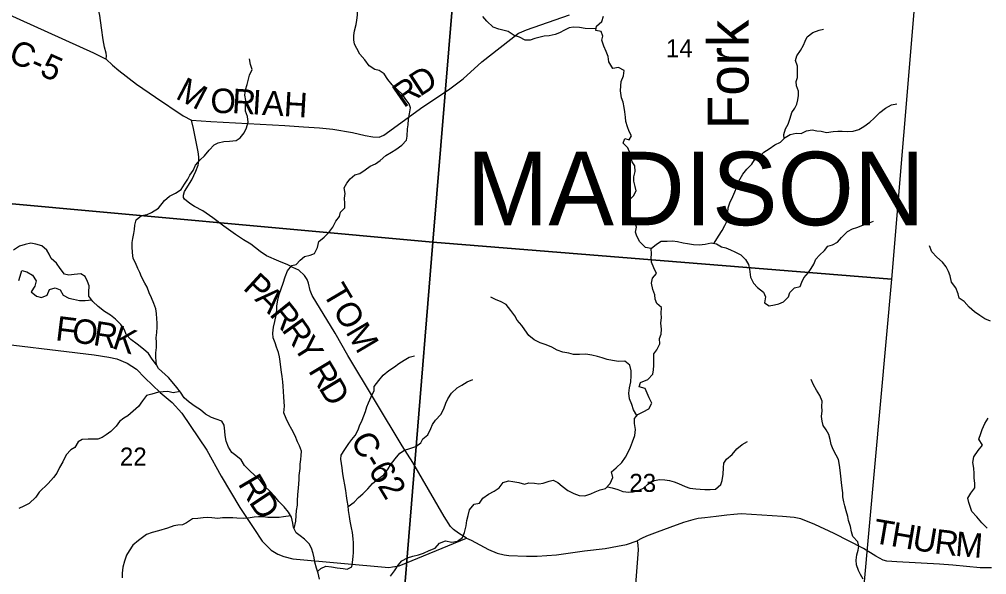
# Model space of a CAD drawing. Extents: x 1715311 to 2083412, y 146837 to 553079.
# Drawn here: x 1966796 to 1978656, y 325907 to 332710 of the extents above; entities that cross this region are included whole.
import ezdxf

# ---------------------------------------------------------------- set-up
doc = ezdxf.new("R2010")
doc.units = 0
for name, color, linetype in [('GM_X_County_Road', 7, 'Continuous'), ('GM_X_County_Road_Text', 7, 'Continuous'), ('GM_X_Major_River', 7, 'Continuous'), ('GM_X_Minor_River', 7, 'Continuous'), ('GM_X_Minor_River_Text', 7, 'Continuous'), ('GM_X_Section', 7, 'Continuous'), ('GM_X_Section_Text', 7, 'Continuous'), ('GM_X_Township_Road', 7, 'Continuous'), ('GM_X_Township_Text', 7, 'Continuous')]:
    doc.layers.add(name, color=color, linetype=linetype)

msp = doc.modelspace()

# ---------------------------------------------------------------- linework, layer by layer
at = {"layer": 'GM_X_County_Road'}
for points in [[(1966408, 332883), (1967704, 332299), (1967860, 332222), (1967939, 332149), (1968017, 332084), (1968232, 331916), (1968466, 331757), (1968805, 331529), (1968909, 331475), (1969143, 331460), (1970051, 331409), (1970280, 331392), (1970478, 331381), (1970638, 331365), (1970883, 331325), (1971035, 331288), (1971129, 331272), (1971206, 331267), (1971265, 331293), (1971743, 331640), (1972058, 331846), (1972236, 331982), (1972468, 332189), (1972918, 332541), (1972927, 332547), (1973014, 332580), (1973541, 332765)], [(1972278, 326354), (1972180, 326416), (1972118, 326459), (1972083, 326499), (1972006, 326618), (1971619, 327282), (1971491, 327486), (1970825, 328593), (1970667, 328866), (1970386, 329326), (1970362, 329390), (1970342, 329477), (1970326, 329523), (1970293, 329574), (1970224, 329636), (1970151, 329671), (1970089, 329703), (1969976, 329746), (1969827, 329811), (1969750, 329865), (1969634, 329955), (1969546, 330009), (1969446, 330073), (1969305, 330178), (1969168, 330278), (1969045, 330363), (1968942, 330418), (1968888, 330453), (1968820, 330506), (1968809, 330528), (1968808, 330557), (1968820, 330601), (1968910, 330746), (1968961, 330850), (1968987, 330923), (1968995, 330971), (1968998, 331025), (1968987, 331088), (1968932, 331373), (1968909, 331475)], [(1966283, 328773), (1967714, 328602), (1967894, 328571), (1967993, 328553), (1968119, 328499), (1968232, 328425), (1968334, 328319), (1968524, 328138), (1968670, 328015), (1968787, 327887), (1969095, 327433), (1969272, 327115), (1969501, 326728), (1969673, 326474), (1969775, 326319), (1969884, 326207), (1969965, 326160), (1970041, 326129), (1970148, 326100), (1971326, 325996), (1971373, 326001), (1971455, 326017), (1972278, 326354), (1972335, 326328), (1972548, 326214), (1972655, 326171), (1972739, 326152), (1972798, 326141), (1973013, 326132), (1973147, 326132), (1973382, 326152), (1973727, 326198), (1973978, 326226), (1974131, 326257), (1974239, 326278), (1974373, 326323)], [(1978715, 325990), (1978577, 325991), (1978242, 326024), (1978078, 326034), (1977555, 326063), (1977434, 326073), (1977386, 326085), (1977299, 326133), (1977148, 326226), (1976785, 326413), (1976551, 326520), (1976378, 326593), (1976297, 326609), (1976154, 326621), (1975646, 326651), (1975556, 326644), (1975471, 326636), (1975339, 326618), (1975202, 326603), (1975118, 326595), (1975052, 326578), (1974939, 326545), (1974771, 326485), (1974617, 326426), (1974484, 326378), (1974424, 326350), (1974373, 326323)], [(1974373, 326323), (1974379, 326269), (1974384, 326213), (1974369, 326000), (1974328, 325473), (1974250, 324475), (1974213, 324320), (1974150, 324192), (1973708, 323550), (1973679, 323470), (1973661, 323312), (1973480, 321714), (1973497, 321615)]]:
    msp.add_lwpolyline(points, dxfattribs=at)
at = {"layer": 'GM_X_Major_River'}
for points in [[(1968504, 328434), (1968476, 328478), (1968424, 328549), (1968378, 328615), (1968319, 328671), (1968239, 328732), (1968162, 328788), (1968106, 328848), (1968084, 328905), (1968041, 328973), (1967975, 329039), (1967912, 329088), (1967840, 329132), (1967762, 329194), (1967699, 329253), (1967649, 329317), (1967647, 329367), (1967652, 329447), (1967632, 329499), (1967602, 329561), (1967551, 329594), (1967469, 329586), (1967403, 329576), (1967349, 329590), (1967297, 329659), (1967250, 329723), (1967188, 329779), (1967162, 329833), (1967133, 329884), (1967071, 329934), (1966999, 329954), (1966939, 329967), (1966868, 329953), (1966800, 329931), (1966726, 329881)], [(1970475, 325853), (1970459, 325925), (1970439, 325987), (1970421, 326061), (1970409, 326115), (1970397, 326165), (1970379, 326233), (1970349, 326285), (1970291, 326343), (1970241, 326381), (1970191, 326421), (1970159, 326485), (1970151, 326539), (1970133, 326611), (1970098, 326673), (1970042, 326737), (1969978, 326803), (1969928, 326865), (1969862, 326933), (1969802, 326991), (1969750, 327059), (1969682, 327123), (1969618, 327183), (1969556, 327245), (1969518, 327315), (1969452, 327365), (1969402, 327403), (1969360, 327469), (1969330, 327541), (1969318, 327611), (1969314, 327663), (1969306, 327737), (1969279, 327787), (1969208, 327813), (1969152, 327833), (1969080, 327875), (1969018, 327925), (1968952, 327969), (1968880, 328019), (1968818, 328074), (1968774, 328143), (1968727, 328199), (1968669, 328268), (1968627, 328322), (1968504, 328434)]]:
    msp.add_lwpolyline(points, dxfattribs=at)
at = {"layer": 'GM_X_Minor_River'}
for points in [[(1970907, 332405), (1970896, 332461), (1970896, 332513), (1970906, 332571), (1970928, 332647), (1970936, 332702), (1970944, 332760), (1970942, 332818), (1970936, 332878), (1970937, 332932), (1970949, 333004), (1970969, 333074), (1971001, 333134), (1970981, 333206), (1970983, 333266), (1970985, 333341), (1970969, 333399), (1970933, 333465), (1970902, 333533), (1970822, 333597), (1970746, 333663), (1970700, 333727), (1970658, 333785), (1970602, 333842)], [(1973868, 332594), (1973734, 332599), (1973666, 332609), (1973592, 332613), (1973538, 332605), (1973481, 332576), (1973419, 332546), (1973367, 332526), (1973293, 332510), (1973233, 332504), (1973181, 332490), (1973115, 332474), (1973061, 332455), (1972998, 332457), (1972930, 332493), (1972864, 332513), (1972788, 332561), (1972726, 332577), (1972674, 332589), (1972604, 332613), (1972530, 332687), (1972480, 332745)], [(1974563, 329402), (1974547, 329478), (1974561, 329540), (1974607, 329598), (1974575, 329664), (1974546, 329734), (1974544, 329785), (1974546, 329837), (1974542, 329903), (1974472, 329917), (1974406, 329983), (1974366, 330053), (1974352, 330103), (1974362, 330165), (1974340, 330233), (1974276, 330307), (1974266, 330377), (1974274, 330439), (1974275, 330493), (1974325, 330549), (1974361, 330611), (1974345, 330661), (1974331, 330729), (1974329, 330780), (1974347, 330846), (1974343, 330914), (1974308, 330966), (1974294, 331016), (1974284, 331066), (1974256, 331136), (1974198, 331194), (1974222, 331250), (1974274, 331234), (1974302, 331284), (1974274, 331336), (1974252, 331394), (1974234, 331460), (1974230, 331510), (1974221, 331578), (1974213, 331631), (1974199, 331697), (1974179, 331747), (1974165, 331833), (1974171, 331897), (1974177, 331949), (1974203, 332019), (1974211, 332085), (1974143, 332121), (1974075, 332109), (1974023, 332191), (1974016, 332255), (1973992, 332317), (1973962, 332381), (1973940, 332455), (1973950, 332505), (1973928, 332561), (1973864, 332575), (1973874, 332627), (1973938, 332684), (1973960, 332748)], [(1976173, 331248), (1976171, 331298), (1976191, 331370), (1976221, 331428), (1976247, 331500), (1976269, 331567), (1976304, 331621), (1976328, 331671), (1976342, 331723), (1976348, 331779), (1976348, 331831), (1976326, 331897), (1976320, 331947), (1976338, 331999), (1976336, 332069), (1976339, 332136), (1976313, 332204), (1976331, 332262), (1976373, 332330), (1976409, 332392), (1976433, 332444), (1976457, 332498), (1976526, 332548), (1976602, 332577), (1976654, 332591)], [(1970166, 326471), (1970187, 326563), (1970192, 326633), (1970196, 326693), (1970206, 326759), (1970206, 326811), (1970210, 326890), (1970220, 326966), (1970224, 327020), (1970226, 327072), (1970229, 327122), (1970239, 327206), (1970241, 327260), (1970247, 327316), (1970253, 327366), (1970255, 327420), (1970233, 327484), (1970205, 327534), (1970179, 327607), (1970138, 327685), (1970100, 327751), (1970068, 327819), (1970040, 327889), (1970046, 327971), (1970044, 328023), (1970040, 328085), (1970036, 328153), (1970032, 328217), (1970026, 328271), (1970019, 328335), (1970011, 328389), (1970003, 328449), (1969993, 328518), (1969985, 328574), (1969973, 328630), (1969949, 328696), (1969931, 328746), (1969907, 328808), (1969903, 328866), (1969914, 328940), (1969928, 329008), (1969946, 329088), (1969952, 329150), (1969954, 329200), (1969964, 329269), (1969982, 329341), (1970029, 329477), (1970057, 329555), (1970085, 329629), (1970137, 329694), (1970191, 329706), (1970238, 329758), (1970292, 329806), (1970364, 329822), (1970416, 329842), (1970452, 329916), (1970470, 329987), (1970535, 330041), (1970591, 330097), (1970641, 330163), (1970677, 330237), (1970723, 330296), (1970735, 330346), (1970786, 330402), (1970788, 330454), (1970784, 330518), (1970790, 330578), (1970778, 330646), (1970812, 330702), (1970852, 330755), (1970908, 330805), (1970971, 330821), (1971037, 330865), (1971097, 330913), (1971165, 330941), (1971221, 330980), (1971291, 331042), (1971360, 331082), (1971412, 331114), (1971484, 331170), (1971544, 331231), (1971552, 331281), (1971556, 331367), (1971563, 331419), (1971569, 331487), (1971581, 331553), (1971591, 331625), (1971577, 331675), (1971525, 331741), (1971493, 331791), (1971429, 331851), (1971369, 331907), (1971313, 331975), (1971271, 332041), (1971207, 332083), (1971155, 332095), (1971087, 332139), (1971031, 332213), (1970969, 332285), (1970935, 332353), (1970907, 332405)], [(1968504, 330396), (1968575, 330490), (1968637, 330542), (1968711, 330580), (1968781, 330626), (1968823, 330692), (1968864, 330751), (1968886, 330801), (1968926, 330859), (1968958, 330923), (1969012, 330989), (1969066, 331037), (1969125, 331108), (1969183, 331172), (1969235, 331196), (1969303, 331214), (1969371, 331216), (1969453, 331226), (1969505, 331259), (1969554, 331321), (1969580, 331383), (1969600, 331449), (1969594, 331519), (1969568, 331585), (1969568, 331651), (1969572, 331717), (1969560, 331781), (1969571, 331846), (1969589, 331912), (1969605, 331976), (1969617, 332026), (1969649, 332094), (1969631, 332158), (1969617, 332226)], [(1975317, 329967), (1975369, 330053), (1975415, 330125), (1975448, 330183), (1975472, 330235), (1975484, 330291), (1975484, 330349), (1975486, 330401), (1975506, 330463), (1975546, 330540), (1975569, 330598), (1975589, 330648), (1975601, 330700), (1975633, 330756), (1975667, 330812), (1975717, 330876), (1975779, 330937), (1975808, 330991), (1975872, 331025), (1975926, 331081), (1975988, 331125), (1976060, 331172), (1976128, 331204), (1976187, 331262), (1976249, 331300), (1976319, 331314), (1976383, 331312), (1976447, 331345), (1976517, 331355), (1976573, 331345), (1976629, 331341), (1976694, 331325), (1976774, 331335), (1976832, 331339), (1976886, 331339), (1976948, 331336), (1977018, 331340), (1977088, 331360), (1977152, 331396), (1977226, 331452), (1977277, 331498), (1977345, 331567), (1977417, 331621), (1977489, 331663), (1977557, 331675)], [(1968479, 328473), (1968468, 328571), (1968470, 328623), (1968479, 328689), (1968479, 328757), (1968475, 328809), (1968481, 328875), (1968486, 328941), (1968486, 328991), (1968482, 329041), (1968476, 329107), (1968469, 329163), (1968445, 329231), (1968415, 329297), (1968388, 329358), (1968362, 329428), (1968334, 329478), (1968295, 329554), (1968275, 329608), (1968251, 329658), (1968220, 329729), (1968192, 329779), (1968184, 329855), (1968181, 329923), (1968179, 329975), (1968189, 330027), (1968199, 330085), (1968209, 330137), (1968214, 330189), (1968228, 330253), (1968294, 330307), (1968364, 330320), (1968416, 330344), (1968504, 330396)], [(1974542, 329901), (1974610, 329957), (1974666, 329991), (1974738, 329993), (1974804, 329997), (1974864, 329987), (1974935, 329974), (1974989, 329964), (1975063, 329952), (1975133, 329948), (1975207, 329956), (1975277, 329974), (1975345, 329962), (1975405, 329924), (1975459, 329913), (1975515, 329887), (1975569, 329863), (1975643, 329827), (1975701, 329769), (1975735, 329707), (1975749, 329651), (1975761, 329551), (1975799, 329479), (1975847, 329427), (1975919, 329369), (1975945, 329309), (1975933, 329236), (1975989, 329199), (1976055, 329211), (1976109, 329225), (1976165, 329249), (1976225, 329311), (1976243, 329365), (1976299, 329423), (1976370, 329438), (1976390, 329490), (1976414, 329544), (1976472, 329608), (1976506, 329658), (1976536, 329712), (1976562, 329771), (1976607, 329823), (1976669, 329877), (1976711, 329933), (1976767, 329949), (1976827, 329979), (1976877, 330038), (1976952, 330110), (1977012, 330142), (1977064, 330160), (1977140, 330190), (1977206, 330212), (1977270, 330239)], [(1978704, 329012), (1978636, 329042), (1978574, 329082), (1978506, 329125), (1978440, 329183), (1978382, 329253), (1978320, 329295), (1978308, 329349), (1978280, 329423), (1978226, 329491), (1978208, 329570), (1978190, 329620), (1978160, 329680), (1978114, 329736), (1978047, 329796), (1977985, 329862), (1977957, 329934)], [(1966790, 329511), (1966808, 329563), (1966826, 329633), (1966890, 329619), (1966956, 329576), (1967001, 329506), (1966985, 329442), (1966943, 329372), (1967005, 329318), (1967068, 329304), (1967136, 329331), (1967165, 329401), (1967234, 329419), (1967298, 329395), (1967334, 329330), (1967404, 329294), (1967461, 329284), (1967535, 329267), (1967605, 329267), (1967683, 329272)], [(1971346, 325890), (1971398, 325953), (1971442, 326025), (1971484, 326075), (1971555, 326115), (1971621, 326133), (1971689, 326149), (1971753, 326170), (1971823, 326204), (1971893, 326232), (1971947, 326294), (1972020, 326322), (1972098, 326306), (1972170, 326319), (1972230, 326361), (1972256, 326423), (1972274, 326505), (1972282, 326571), (1972299, 326633), (1972315, 326703), (1972373, 326772), (1972437, 326782), (1972481, 326846), (1972549, 326894), (1972616, 326930), (1972678, 326969), (1972728, 327035), (1972794, 327055), (1972846, 327049), (1972922, 327037), (1972988, 327015), (1973044, 327033), (1973114, 327030), (1973166, 327020), (1973219, 327030), (1973291, 327054), (1973343, 327066), (1973399, 327038), (1973451, 326990), (1973523, 326940), (1973595, 326902), (1973659, 326876), (1973729, 326871), (1973803, 326897), (1973857, 326921), (1973919, 326947), (1973984, 326963), (1974042, 327023), (1974074, 327098), (1974058, 327166), (1974114, 327216), (1974182, 327280), (1974229, 327348), (1974259, 327406), (1974289, 327467), (1974313, 327533), (1974341, 327611), (1974351, 327685), (1974340, 327759), (1974340, 327821), (1974378, 327871), (1974444, 327902), (1974514, 327940), (1974550, 328008), (1974518, 328072), (1974492, 328130), (1974468, 328188), (1974396, 328210), (1974411, 328262), (1974501, 328298), (1974563, 328364), (1974571, 328415), (1974575, 328471), (1974577, 328541), (1974575, 328611), (1974612, 328661), (1974648, 328735), (1974644, 328801), (1974666, 328853), (1974668, 328915), (1974662, 328988), (1974668, 329058), (1974667, 329108), (1974671, 329180), (1974611, 329228), (1974591, 329284), (1974587, 329334), (1974563, 329402)], [(1974366, 327855), (1974328, 327925), (1974306, 327993), (1974278, 328061), (1974270, 328130), (1974278, 328194), (1974294, 328268), (1974297, 328342), (1974297, 328406), (1974283, 328472), (1974221, 328522), (1974141, 328520), (1974067, 328532), (1974005, 328542), (1973942, 328562), (1973886, 328579), (1973814, 328597), (1973742, 328607), (1973664, 328603), (1973592, 328605), (1973534, 328621), (1973458, 328631), (1973392, 328657), (1973326, 328694), (1973256, 328724), (1973184, 328746), (1973110, 328782), (1973042, 328838), (1972996, 328908), (1972956, 328960), (1972902, 329026), (1972870, 329078), (1972824, 329142), (1972766, 329216), (1972704, 329248), (1972636, 329280), (1972576, 329306)], [(1970452, 325946), (1970491, 325981), (1970555, 326011), (1970623, 326005), (1970693, 325989), (1970765, 325981), (1970817, 325973), (1970871, 326002), (1970879, 326058), (1970890, 326128), (1970892, 326180), (1970892, 326298), (1970890, 326348), (1970880, 326422), (1970870, 326482), (1970852, 326564), (1970844, 326620), (1970833, 326693), (1970827, 326751), (1970817, 326815), (1970809, 326873), (1970801, 326939), (1970787, 327009), (1970773, 327071), (1970763, 327141), (1970753, 327217), (1970746, 327267), (1970740, 327323), (1970742, 327373), (1970786, 327442), (1970838, 327512), (1970872, 327562), (1970914, 327612), (1970949, 327682), (1970967, 327732), (1970999, 327800), (1971039, 327905), (1971057, 327963), (1971077, 328013), (1971110, 328085), (1971146, 328163), (1971148, 328213), (1971204, 328284), (1971258, 328350), (1971325, 328410), (1971397, 328452), (1971449, 328492), (1971513, 328533), (1971575, 328573), (1971643, 328587)], [(1970828, 326741), (1970901, 326795), (1970955, 326853), (1971007, 326899), (1971069, 326957), (1971126, 327024), (1971192, 327078), (1971264, 327132), (1971320, 327202), (1971348, 327254), (1971405, 327327), (1971463, 327395), (1971517, 327431), (1971585, 327453), (1971657, 327477), (1971719, 327522), (1971744, 327572), (1971804, 327622), (1971842, 327696), (1971862, 327748), (1971898, 327798), (1971966, 327871), (1972001, 327937), (1972025, 328007), (1972051, 328063), (1972095, 328129), (1972163, 328195), (1972221, 328228), (1972288, 328270), (1972356, 328300)], [(1977144, 325850), (1977110, 325908), (1977084, 325960), (1977062, 326028), (1977058, 326084), (1977066, 326152), (1977082, 326206), (1977089, 326256), (1977075, 326308), (1977015, 326374), (1977001, 326430), (1976985, 326497), (1976963, 326569), (1976955, 326619), (1976933, 326691), (1976917, 326749), (1976905, 326799), (1976893, 326859), (1976891, 326911), (1976884, 326965), (1976878, 327035), (1976868, 327113), (1976860, 327189), (1976854, 327247), (1976840, 327317), (1976810, 327371), (1976776, 327440), (1976752, 327500), (1976736, 327562), (1976723, 327624), (1976689, 327680), (1976653, 327736), (1976639, 327786), (1976633, 327846), (1976639, 327916), (1976637, 327966), (1976641, 328034), (1976613, 328100), (1976569, 328168), (1976535, 328234), (1976506, 328298)], [(1968504, 328144), (1968420, 328118), (1968356, 328101), (1968308, 328037), (1968256, 327969), (1968128, 327854), (1968076, 327824), (1968026, 327782), (1967985, 327728), (1967919, 327660), (1967861, 327621), (1967811, 327587), (1967759, 327565), (1967707, 327565), (1967638, 327566), (1967566, 327562), (1967516, 327534), (1967477, 327464), (1967427, 327436), (1967371, 327375), (1967331, 327291), (1967289, 327221), (1967255, 327149), (1967214, 327097), (1967148, 327023), (1967040, 326916), (1967000, 326858), (1966918, 326780), (1966850, 326747), (1966788, 326719)], [(1968768, 328149), (1968684, 328134), (1968616, 328152), (1968504, 328144)], [(1978661, 326478), (1978597, 326544), (1978535, 326616), (1978475, 326682), (1978453, 326742), (1978439, 326792), (1978425, 326844), (1978462, 326906), (1978512, 326972), (1978510, 327022), (1978504, 327092), (1978504, 327145), (1978498, 327211), (1978486, 327283), (1978499, 327351), (1978553, 327427), (1978605, 327495), (1978559, 327565), (1978585, 327635), (1978603, 327686), (1978635, 327758), (1978676, 327824)], [(1974006, 326985), (1974064, 326971), (1974134, 326952), (1974196, 326926), (1974268, 326918), (1974322, 326922), (1974376, 326936), (1974450, 326968), (1974504, 327016), (1974581, 327061), (1974649, 327073), (1974711, 327067), (1974767, 327059), (1974825, 327045), (1974879, 327023), (1974961, 326987), (1975017, 326967), (1975091, 326957), (1975145, 326956), (1975201, 326950), (1975265, 326950), (1975333, 326954), (1975398, 327010), (1975412, 327062), (1975426, 327140), (1975428, 327214), (1975432, 327273), (1975466, 327323), (1975536, 327379), (1975593, 327447), (1975659, 327503), (1975725, 327540)], [(1970124, 326626), (1970037, 326615), (1969983, 326609), (1969843, 326608), (1969785, 326614), (1969727, 326614), (1969675, 326610), (1969603, 326600), (1969543, 326594), (1969463, 326598), (1969412, 326604), (1969286, 326603), (1969230, 326597), (1969158, 326603), (1969106, 326607), (1969050, 326603), (1968984, 326597), (1968920, 326591), (1968846, 326542), (1968795, 326518), (1968741, 326512), (1968689, 326504), (1968613, 326478), (1968504, 326443)], [(1968504, 326443), (1968425, 326425), (1968357, 326399), (1968307, 326364), (1968257, 326326), (1968187, 326270), (1968141, 326200), (1968112, 326146), (1968084, 326074), (1968066, 325998), (1968057, 325924), (1968055, 325868)]]:
    msp.add_lwpolyline(points, dxfattribs=at)
at = {"layer": 'GM_X_Section'}
for points in [[(1966674, 335761), (1972308, 335314), (1971868, 329980), (1966301, 330486)], [(1972308, 335314), (1977934, 334862), (1977491, 329528), (1971868, 329980)], [(1966301, 330486), (1971868, 329980), (1971432, 324673), (1965819, 325096)], [(1971868, 329980), (1977491, 329528), (1977007, 324197), (1971432, 324673)]]:
    msp.add_lwpolyline(points, close=True, dxfattribs=at)
at = {"layer": 'GM_X_Township_Road'}
msp.add_lwpolyline([(1967860, 332222), (1967864, 332265), (1967860, 332296), (1967842, 332370), (1967824, 332460), (1967803, 332607), (1967782, 332757), (1967755, 332883), (1967745, 332974), (1967739, 333084), (1967747, 333238), (1967774, 333378), (1967811, 333517), (1967846, 333637), (1967857, 333726), (1967837, 333846), (1967737, 334198), (1967671, 334421)], dxfattribs=at)

# ---------------------------------------------------------------- texts
at = {"layer": 'GM_X_County_Road_Text'}
for s, rotation, p in [('C-5', 335.8987, (1966646, 332204)), ('D', 33.0546, (1971707, 331757)), ('M', 332.5314, (1968698, 331747)), ('R', 34.7174, (1971507, 331618)), ('O', 0.5143, (1969141, 331560)), ('R', 356.5164, (1969399, 331563)), ('I', 356.5162, (1969645, 331548)), ('A', 356.5171, (1969768, 331540)), ('H', 356.7855, (1970033, 331524)), ('P', 317.4467, (1969526, 329409)), ('TOM', 300.5908, (1970507, 329361)), ('A', 314.9227, (1969672, 329274)), ('R', 308.8476, (1969853, 329094)), ('F', 352.9357, (1967230, 328780)), ('O', 352.6726, (1967430, 328755)), ('R', 350.9426, (1967690, 328722)), ('R', 305.3585, (1970005, 328906)), ('K', 341.7943, (1967921, 328686)), ('Y', 302.1046, (1970145, 328708)), ('R', 301.0187, (1970332, 328407)), ('D', 301.0056, (1970459, 328196)), ('C-62', 301.1915, (1970848, 327548)), ('R', 300.4604, (1969470, 327022)), ('D', 303.4322, (1969603, 326796)), ('T', 350.2981, (1977250, 326298)), ('H', 350.2969, (1977471, 326260)), ('U', 350.5767, (1977733, 326215)), ('R', 352.9349, (1978006, 326170)), ('M', 355.2721, (1978264, 326138))]:
    msp.add_text(s, height=300, rotation=rotation, dxfattribs=at).set_placement(p)
at = {"layer": 'GM_X_Minor_River_Text'}
msp.add_text('Fork', height=500, rotation=90.0002, dxfattribs=at).set_placement((1975737, 331367))
at = {"layer": 'GM_X_Section_Text'}
for s, p in [('14', (1974724, 332246)), ('22', (1968029, 327243)), ('23', (1974275, 326921))]:
    msp.add_text(s, height=221, rotation=0, dxfattribs=at).set_placement(p)
at = {"layer": 'GM_X_Township_Text'}
msp.add_text('MADISON', height=900, rotation=0, dxfattribs=at).set_placement((1972281, 330188))

doc.saveas('drawing.dxf')
